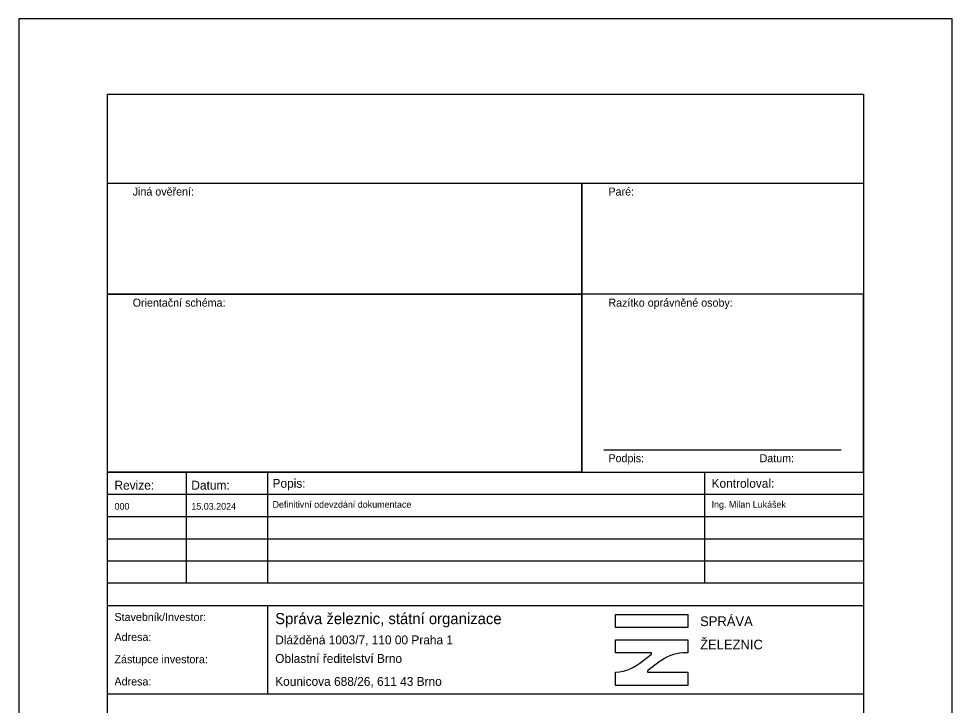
# Model space of a CAD drawing. Extents: x -172 to -151, y 333 to 362.7.
# Drawn here: x -172 to -151, y 347.25 to 362.7 of the extents above; entities that cross this region are included whole.
import ezdxf

# ---------------------------------------------------------------- set-up
doc = ezdxf.new("R2010")
doc.units = 0
for name, color, linetype in [('Default', 7, 'Continuous'), ('Rozpiska_Logo', 7, 'Continuous'), ('Rozpiska_pola_3', 7, 'Continuous'), ('Rozpiska_pole_1', 7, 'Continuous'), ('Rozpiska_pole_2', 7, 'Continuous'), ('Rozpiska_pole_4', 7, 'Continuous'), ('Rozpiska_pole_5', 7, 'Continuous'), ('Rozpiska_pole_6', 7, 'Continuous')]:
    doc.layers.add(name, color=color, linetype=linetype)

msp = doc.modelspace()

# ---------------------------------------------------------------- linework, layer by layer
at = {"layer": 'Default'}
for p, q in [((-151, 362.7), (-172, 362.7)), ((-172, 362.7), (-172, 333)), ((-151, 333), (-151, 362.7)), ((-159.335, 352.5), (-159.335, 359))]:
    msp.add_line(p, q, dxfattribs=at)
msp.add_lwpolyline([(-172, 333), (-151, 333), (-151, 362.7), (-172, 362.7)], close=True, dxfattribs=at)
at = {"layer": 'Rozpiska_Logo'}
for p, q in [((-157.96, 348.253), (-157.766, 348.399)), ((-157.766, 348.399), (-157.766, 348.434)), ((-157.597, 348.226), (-157.858, 348.024)), ((-157.858, 348.024), (-157.858, 347.993))]:
    msp.add_line(p, q, dxfattribs=at)
msp.add_lwpolyline([(-158.578, 349.291), (-156.948, 349.291), (-156.948, 348.998), (-158.578, 348.998)], close=True, dxfattribs=at)
for points in [[(-157.766, 348.434), (-158.578, 348.434), (-158.578, 348.727), (-156.948, 348.727), (-156.948, 348.434), (-157.056, 348.434)], [(-157.858, 347.993), (-156.948, 347.993), (-156.948, 347.7), (-158.578, 347.7), (-158.578, 347.993), (-158.572, 347.993)]]:
    msp.add_lwpolyline(points, dxfattribs=at)
for centre, radius, start, end in [((-156.982, 347.432), 1.004, 94.2142, 127.7808), ((-158.656, 349.042), 1.052, 274.6014, 311.4254)]:
    msp.add_arc(centre, radius, start, end, dxfattribs=at)
at = {"layer": 'Rozpiska_pola_3'}
msp.add_line((-158.835, 353), (-153.5, 353), dxfattribs=at)
at = {"layer": 'Rozpiska_pole_1'}
msp.add_lwpolyline([(-170, 361), (-153, 361), (-153, 334.5), (-170, 334.5)], close=True, dxfattribs=at)
at = {"layer": 'Rozpiska_pole_2'}
for points in [[(-170, 359), (-159.335, 359), (-159.335, 356.5), (-170, 356.5)], [(-159.335, 359), (-153, 359), (-153, 356.5), (-159.335, 356.5)], [(-170, 356.5), (-159.335, 356.5), (-159.335, 352.5), (-170, 352.5)], [(-153, 356.5), (-159.335, 356.5), (-159.335, 352.5), (-153, 352.5)]]:
    msp.add_lwpolyline(points, close=True, dxfattribs=at)
at = {"layer": 'Rozpiska_pole_4'}
for p, q in [((-168.223, 350), (-168.223, 352.5)), ((-166.395, 350), (-166.395, 352.5)), ((-156.57, 350), (-156.57, 352.5)), ((-170, 352), (-153, 352)), ((-170, 351.5), (-153, 351.5)), ((-170, 351), (-153, 351)), ((-170, 350.5), (-153, 350.5))]:
    msp.add_line(p, q, dxfattribs=at)
msp.add_lwpolyline([(-170, 352.5), (-153, 352.5), (-153, 350), (-170, 350)], close=True, dxfattribs=at)
at = {"layer": 'Rozpiska_pole_5'}
msp.add_line((-166.395, 347.5), (-166.395, 349.5), dxfattribs=at)
msp.add_lwpolyline([(-170, 349.5), (-153, 349.5), (-153, 347.5), (-170, 347.5)], close=True, dxfattribs=at)

# ---------------------------------------------------------------- texts
at = {"layer": 'Rozpiska_pola_3'}
for s, p in [('Paré:', (-158.735, 358.72)), ('Razítko oprávněné osoby:', (-158.735, 356.22)), ('Podpis:', (-158.735, 352.72)), ('Datum:', (-155.335, 352.72))]:
    msp.add_text(s, height=0.18, dxfattribs=at).set_placement(p)
at = {"layer": 'Rozpiska_pole_2'}
for s, p in [('Jiná ověření:', (-169.435, 358.72)), ('Orientační schéma:', (-169.435, 356.22))]:
    msp.add_text(s, height=0.18, dxfattribs=at).set_placement(p)
at = {"layer": 'Rozpiska_pole_4'}
for s, height, p in [('Revize:', 0.2, (-169.845, 352.103)), ('Datum:', 0.2, (-168.116, 352.103)), ('Popis:', 0.2, (-166.29, 352.145)), ('Kontroloval:', 0.2, (-156.415, 352.145)), ('000', 0.15, (-169.845, 351.653)), ('15.03.2024', 0.15, (-168.116, 351.653)), ('Definitivní odevzdání dokumentace', 0.15, (-166.29, 351.695)), ('Ing. Milan Lukášek', 0.15, (-156.415, 351.695))]:
    msp.add_text(s, height=height, dxfattribs=at).set_placement(p)
at = {"layer": 'Rozpiska_pole_5'}
for s, height, p in [('Stavebník/Investor:', 0.18, (-169.845, 349.147)), ('Správa železnic, státní organizace', 0.25, (-166.23, 349.077)), ('Adresa:', 0.18, (-169.845, 348.697)), ('Zástupce investora:', 0.18, (-169.845, 348.197)), ('Adresa:', 0.18, (-169.845, 347.697))]:
    msp.add_text(s, height=height, dxfattribs=at).set_placement(p)
at = {"layer": 'Rozpiska_pole_6'}
for s, height, p in [('SPRÁVA', 0.2183, (-156.673, 349.033)), ('Dlážděná 1003/7, 110 00 Praha 1', 0.2, (-166.23, 348.622)), ('ŽELEZNIC', 0.2183, (-156.673, 348.509)), ('Oblastní ředitelství Brno', 0.2, (-166.23, 348.204)), ('Kounicova 688/26, 611 43 Brno', 0.2, (-166.23, 347.688))]:
    msp.add_text(s, height=height, dxfattribs=at).set_placement(p)

doc.saveas('drawing.dxf')
